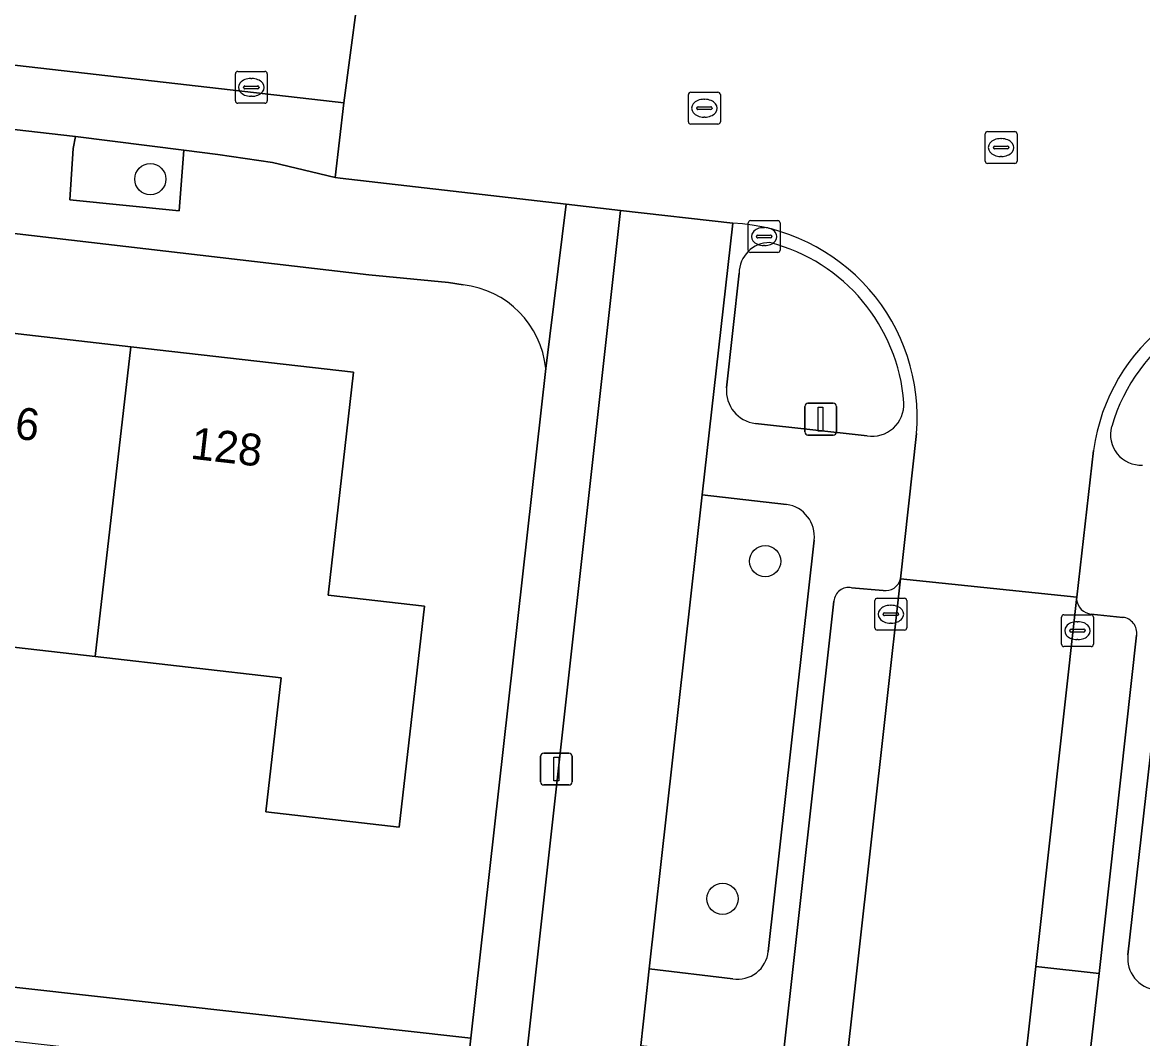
# Model space of a CAD drawing. Extents: x 162026 to 163502, y 387295 to 388169.
# Drawn here: x 162277.28 to 162312.4, y 387953.87 to 387985.75 of the extents above; entities that cross this region are included whole.
import ezdxf

# ---------------------------------------------------------------- set-up
doc = ezdxf.new("R2010")
doc.units = 0
for name, color, linetype in [('IMGEO_Berm_groen', 7, 'Continuous'), ('IMGEO_Boom', 7, 'Continuous'), ('IMGEO_Erf', 7, 'Continuous'), ('IMGEO_Fietspad_gesloten', 7, 'Continuous'), ('IMGEO_Groenvoorziening', 7, 'Continuous'), ('IMGEO_Kolk', 7, 'Continuous'), ('IMGEO_Lichtmast', 7, 'Continuous'), ('IMGEO_Pand', 7, 'Continuous'), ('IMGEO_Pand_nummerreeks', 7, 'Continuous'), ('IMGEO_Parkeervlak_open', 7, 'Continuous'), ('IMGEO_Rijbaan_lokaal_gesloten', 7, 'Continuous'), ('IMGEO_Rijbaan_lokaal_open', 7, 'Continuous'), ('IMGEO_Rioolput', 7, 'Continuous'), ('IMGEO_Voetpad_open', 7, 'Continuous')]:
    doc.layers.add(name, color=color, linetype=linetype)

msp = doc.modelspace()

# ---------------------------------------------------------------- linework, layer by layer
at = {"layer": 'IMGEO_Berm_groen'}
for points in [[(162301.234, 387970.629), (162298.595, 387970.931), (162296.932, 387956.066), (162299.551, 387955.754)], [(162300.663, 387956.611), (162302.1, 387969.506)]]:
    msp.add_lwpolyline(points, dxfattribs=at)
for centre, radius, start, end in [((162301.092, 387969.624), 1.015, 353.3153, 81.9599), ((162299.706, 387956.703), 0.962, 260.7414, 354.5003)]:
    msp.add_arc(centre, radius, start, end, dxfattribs=at)
at = {"layer": 'IMGEO_Boom'}
for centre in [(162281.289, 387980.833), (162300.567, 387968.849), (162299.23, 387958.261)]:
    msp.add_circle(centre, 0.489, dxfattribs=at)
at = {"layer": 'IMGEO_Erf'}
for points in [[(162291.097, 387977.515), (162290.634, 387977.587), (162288.142, 387977.833), (162261.241, 387980.973), (162256.056, 387981.553)], [(162273.693, 387976.378), (162280.678, 387975.578), (162287.661, 387974.779), (162286.86, 387967.781), (162289.888, 387967.434), (162289.095, 387960.507), (162284.908, 387960.986), (162285.39, 387965.195), (162279.564, 387965.862), (162273.794, 387966.523)], [(162239.605, 387969.039), (162246.536, 387968.264), (162245.755, 387961.273), (162248.918, 387960.92), (162252.845, 387960.481), (162252.599, 387958.276), (162260.704, 387957.306), (162291.341, 387953.887), (162293.685, 387974.891)]]:
    msp.add_lwpolyline(points, dxfattribs=at)
msp.add_arc((162290.771, 387974.605), 2.928, 5.6056, 83.6029, dxfattribs=at)
at = {"layer": 'IMGEO_Fietspad_gesloten'}
msp.add_lwpolyline([(162286.582, 387863.057), (162286.832, 387865.282), (162287.035, 387867.097), (162289.894, 387892.691), (162290.021, 387893.825), (162290.158, 387895.051), (162293.257, 387922.839), (162293.487, 387924.906), (162293.703, 387926.861), (162296.667, 387953.66), (162296.814, 387954.996), (162296.932, 387956.066), (162298.595, 387970.931), (162299.549, 387979.456), (162296.034, 387979.848), (162290.464, 387929.711), (162288.097, 387908.488), (162278.956, 387826.545)], dxfattribs=at)
at = {"layer": 'IMGEO_Groenvoorziening'}
msp.add_lwpolyline([(162282.345, 387981.742), (162278.942, 387982.168), (162278.868, 387981.798), (162278.769, 387980.18), (162282.19, 387979.834)], close=True, dxfattribs=at)
for points in [[(162299.746, 387977.882), (162299.356, 387974.287)], [(162300.263, 387973.168), (162303.759, 387972.782)], [(162313.271, 387968.348), (162311.936, 387956.502)]]:
    msp.add_lwpolyline(points, dxfattribs=at)
for centre, radius, start, end in [((162300.712, 387977.877), 0.966, 90.048, 179.714), ((162299.303, 387973.395), 5.628, 4.346, 75.5071), ((162316.871, 387971.493), 5.666, 84.1002, 163.8486), ((162300.383, 387974.192), 1.031, 174.7224, 263.3303), ((162303.915, 387973.77), 1, 261.0367, 2.9103), ((162312.342, 387972.812), 0.95, 164.3094, 273.3573), ((162312.922, 387956.392), 0.992, 173.6196, 263.649)]:
    msp.add_arc(centre, radius, start, end, dxfattribs=at)
at = {"layer": 'IMGEO_Kolk'}
for p, q in [((162283.955, 387983.285), (162283.955, 387984.137)), ((162284.03, 387984.211), (162284.882, 387984.211)), ((162284.443, 387983.991), (162284.468, 387983.991)), ((162284.956, 387984.137), (162284.956, 387983.285)), ((162284.214, 387983.705), (162284.214, 387983.717)), ((162284.652, 387983.668), (162284.254, 387983.668)), ((162284.257, 387983.754), (162284.655, 387983.754)), ((162284.698, 387983.717), (162284.698, 387983.705)), ((162284.466, 387983.431), (162284.441, 387983.431)), ((162284.882, 387983.211), (162284.03, 387983.211)), ((162300.032, 387978.605), (162300.032, 387979.457)), ((162300.107, 387979.531), (162300.959, 387979.531)), ((162301.033, 387979.457), (162301.033, 387978.605)), ((162300.291, 387979.025), (162300.291, 387979.037)), ((162300.334, 387979.074), (162300.732, 387979.074)), ((162300.52, 387979.311), (162300.545, 387979.311)), ((162300.775, 387979.037), (162300.775, 387979.025)), ((162300.729, 387978.988), (162300.331, 387978.988)), ((162300.543, 387978.751), (162300.518, 387978.751)), ((162300.959, 387978.531), (162300.107, 387978.531)), ((162304.006, 387966.76), (162304.006, 387967.612)), ((162304.081, 387967.686), (162304.933, 387967.686)), ((162304.494, 387967.466), (162304.519, 387967.466)), ((162305.007, 387967.612), (162305.007, 387966.76)), ((162304.265, 387967.18), (162304.265, 387967.192)), ((162304.703, 387967.143), (162304.305, 387967.143)), ((162304.308, 387967.229), (162304.706, 387967.229)), ((162304.749, 387967.192), (162304.749, 387967.18)), ((162309.855, 387966.244), (162309.855, 387967.096)), ((162309.93, 387967.17), (162310.782, 387967.17)), ((162310.856, 387967.096), (162310.856, 387966.244)), ((162304.517, 387966.906), (162304.492, 387966.906)), ((162310.343, 387966.95), (162310.368, 387966.95)), ((162304.933, 387966.686), (162304.081, 387966.686)), ((162310.114, 387966.664), (162310.114, 387966.676)), ((162310.552, 387966.627), (162310.154, 387966.627)), ((162310.157, 387966.713), (162310.555, 387966.713)), ((162310.366, 387966.39), (162310.341, 387966.39)), ((162310.598, 387966.676), (162310.598, 387966.664)), ((162310.782, 387966.17), (162309.93, 387966.17))]:
    msp.add_line(p, q, dxfattribs=at)
for points in [[(162283.955, 387983.285), (162283.955, 387984.137)], [(162284.03, 387984.211), (162284.882, 387984.211)], [(162284.956, 387984.137), (162284.956, 387983.285)], [(162284.882, 387983.211), (162284.03, 387983.211)], [(162300.032, 387978.605), (162300.032, 387979.457)], [(162300.107, 387979.531), (162300.959, 387979.531)], [(162301.033, 387979.457), (162301.033, 387978.605)], [(162300.959, 387978.531), (162300.107, 387978.531)], [(162304.006, 387966.76), (162304.006, 387967.612)], [(162304.081, 387967.686), (162304.933, 387967.686)], [(162305.007, 387967.612), (162305.007, 387966.76)], [(162309.855, 387966.244), (162309.855, 387967.096)], [(162309.93, 387967.17), (162310.782, 387967.17)], [(162310.856, 387967.096), (162310.856, 387966.244)], [(162304.933, 387966.686), (162304.081, 387966.686)], [(162310.782, 387966.17), (162309.93, 387966.17)]]:
    msp.add_lwpolyline(points, dxfattribs=at)
for centre, radius, start, end in [((162284.032, 387984.135), 0.0765, 91.552, 178.448), ((162284.032, 387984.135), 0.0765, 91.552, 178.448), ((162284.88, 387984.135), 0.0765, 1.552, 88.448), ((162284.88, 387984.135), 0.0765, 1.552, 88.448), ((162284.254, 387983.714), 0.0403, 85.8775, 175.7526), ((162284.251, 387983.704), 0.0366, 178.938, 274.7102), ((162284.655, 387983.711), 0.043, 264.8664, 352.4533), ((162284.659, 387983.716), 0.0386, 1.7309, 96.639), ((162284.032, 387983.287), 0.0765, 181.552, 268.448), ((162284.032, 387983.287), 0.0765, 181.552, 268.448), ((162284.88, 387983.287), 0.0765, 271.552, 358.448), ((162284.88, 387983.287), 0.0765, 271.552, 358.448), ((162300.109, 387979.455), 0.0765, 91.552, 178.448), ((162300.109, 387979.455), 0.0765, 91.552, 178.448), ((162300.957, 387979.455), 0.0765, 1.552, 88.448), ((162300.957, 387979.455), 0.0765, 1.552, 88.448), ((162300.331, 387979.034), 0.0403, 85.8775, 175.7526), ((162300.736, 387979.036), 0.0386, 1.7309, 96.639), ((162300.328, 387979.024), 0.0366, 178.938, 274.7102), ((162300.732, 387979.031), 0.043, 264.8664, 352.4533), ((162300.109, 387978.607), 0.0765, 181.552, 268.448), ((162300.109, 387978.607), 0.0765, 181.552, 268.448), ((162300.957, 387978.607), 0.0765, 271.552, 358.448), ((162300.957, 387978.607), 0.0765, 271.552, 358.448), ((162304.083, 387967.61), 0.0765, 91.552, 178.448), ((162304.083, 387967.61), 0.0765, 91.552, 178.448), ((162304.931, 387967.61), 0.0765, 1.552, 88.448), ((162304.931, 387967.61), 0.0765, 1.552, 88.448), ((162304.305, 387967.189), 0.0403, 85.8775, 175.7526), ((162304.302, 387967.179), 0.0366, 178.938, 274.7102), ((162304.706, 387967.186), 0.043, 264.8664, 352.4533), ((162304.71, 387967.191), 0.0386, 1.7309, 96.639), ((162309.932, 387967.094), 0.0765, 91.552, 178.448), ((162309.932, 387967.094), 0.0765, 91.552, 178.448), ((162310.78, 387967.094), 0.0765, 1.552, 88.448), ((162310.78, 387967.094), 0.0765, 1.552, 88.448), ((162304.083, 387966.762), 0.0765, 181.552, 268.448), ((162304.083, 387966.762), 0.0765, 181.552, 268.448), ((162304.931, 387966.762), 0.0765, 271.552, 358.448), ((162304.931, 387966.762), 0.0765, 271.552, 358.448), ((162310.154, 387966.673), 0.0403, 85.8775, 175.7526), ((162310.151, 387966.663), 0.0366, 178.938, 274.7102), ((162310.555, 387966.67), 0.043, 264.8664, 352.4533), ((162310.559, 387966.675), 0.0386, 1.7309, 96.639), ((162309.932, 387966.246), 0.0765, 181.552, 268.448), ((162309.932, 387966.246), 0.0765, 181.552, 268.448), ((162310.78, 387966.246), 0.0765, 271.552, 358.448), ((162310.78, 387966.246), 0.0765, 271.552, 358.448)]:
    msp.add_arc(centre, radius, start, end, dxfattribs=at)
for centre, major_axis, ratio, start_param, end_param in [((162284.442, 387983.711), (-0.387, 0.002), 0.722429, 4.712389, 7.853982), ((162284.467, 387983.711), (-0.39, 0.002), 0.717154, 1.570796, 4.712389), ((162300.519, 387979.031), (-0.387, 0.002), 0.722429, 4.712389, 7.853982), ((162300.544, 387979.031), (-0.39, 0.002), 0.717154, 1.570796, 4.712389), ((162304.493, 387967.186), (-0.387, 0.002), 0.722429, 4.712389, 7.853982), ((162304.518, 387967.186), (-0.39, 0.002), 0.717154, 1.570796, 4.712389), ((162310.342, 387966.67), (-0.387, 0.002), 0.722429, 4.712389, 7.853982), ((162310.367, 387966.67), (-0.39, 0.002), 0.717154, 1.570796, 4.712389)]:
    msp.add_ellipse(centre, major_axis=major_axis, ratio=ratio, start_param=start_param, end_param=end_param, dxfattribs=at)
at = {"layer": 'IMGEO_Lichtmast'}
for p, q in [((162301.907, 387973.802), (162302.697, 387973.802)), ((162302.697, 387973.802), (162301.907, 387973.802)), ((162301.807, 387972.902), (162301.807, 387973.702)), ((162301.807, 387973.702), (162301.807, 387972.902)), ((162302.797, 387973.702), (162302.797, 387972.902)), ((162302.797, 387972.902), (162302.797, 387973.702)), ((162302.697, 387972.802), (162301.907, 387972.802)), ((162301.907, 387972.802), (162302.697, 387972.802)), ((162293.522, 387961.93), (162293.522, 387962.73)), ((162293.522, 387962.73), (162293.522, 387961.93)), ((162293.622, 387962.83), (162294.412, 387962.83)), ((162294.412, 387962.83), (162293.622, 387962.83)), ((162294.512, 387962.73), (162294.512, 387961.93)), ((162294.512, 387961.93), (162294.512, 387962.73)), ((162294.412, 387961.83), (162293.622, 387961.83)), ((162293.622, 387961.83), (162294.412, 387961.83))]:
    msp.add_line(p, q, dxfattribs=at)
for points in [[(162302.227, 387973.677), (162302.377, 387973.677), (162302.377, 387972.927), (162302.227, 387972.927), (162302.227, 387973.677)], [(162293.942, 387962.705), (162294.092, 387962.705), (162294.092, 387961.955), (162293.942, 387961.955), (162293.942, 387962.705)]]:
    msp.add_lwpolyline(points, dxfattribs=at)
for centre, start, end in [((162301.907, 387973.702), 90, 180), ((162301.907, 387973.702), 90, 180), ((162302.697, 387973.702), 0, 90), ((162302.697, 387973.702), 360, 90), ((162301.907, 387972.902), 180, 270), ((162301.907, 387972.902), 180, 270), ((162302.697, 387972.902), 270, 0), ((162302.697, 387972.902), 270, 0), ((162293.622, 387962.73), 90, 180), ((162293.622, 387962.73), 90, 180), ((162294.412, 387962.73), 0, 90), ((162294.412, 387962.73), 360, 90), ((162293.622, 387961.93), 180, 270), ((162293.622, 387961.93), 180, 270), ((162294.412, 387961.93), 270, 0), ((162294.412, 387961.93), 270, 0)]:
    msp.add_arc(centre, 0.1, start, end, dxfattribs=at)
at = {"layer": 'IMGEO_Pand'}
for points in [[(162280.678, 387975.578), (162273.693, 387976.378), (162272.883, 387969.3), (162269.935, 387969.637), (162269.152, 387962.798), (162273.313, 387962.322), (162273.794, 387966.523), (162279.564, 387965.862)], [(162279.564, 387965.862), (162285.39, 387965.195), (162284.908, 387960.986), (162289.095, 387960.507), (162289.888, 387967.434), (162286.86, 387967.781), (162287.661, 387974.779), (162280.678, 387975.578)]]:
    msp.add_lwpolyline(points, close=True, dxfattribs=at)
at = {"layer": 'IMGEO_Parkeervlak_open'}
msp.add_lwpolyline([(162287.36, 387983.225), (162274.652, 387984.68), (162274.447, 387982.68), (162278.942, 387982.168), (162282.345, 387981.742), (162283.404, 387981.609), (162285.117, 387981.352), (162287.087, 387980.885)], close=True, dxfattribs=at)
for points in [[(162302.723, 387967.594), (162294.303, 387892.007), (162291.572, 387867.15), (162293.541, 387866.933), (162296.246, 387891.427), (162304.811, 387968.292)], [(162304.263, 387967.93), (162303.277, 387968.016)], [(162310.325, 387967.647), (162309.047, 387956.134), (162311.038, 387955.913), (162312.212, 387966.528)], [(162311.777, 387967.088), (162310.787, 387967.188)]]:
    msp.add_lwpolyline(points, dxfattribs=at)
for centre, radius, start, end in [((162304.333, 387968.419), 0.494, 261.8083, 345.0879), ((162303.186, 387967.561), 0.464, 78.7022, 175.8932), ((162310.852, 387967.716), 0.532, 187.4211, 262.9522), ((162311.723, 387966.597), 0.494, 351.9363, 83.7428)]:
    msp.add_arc(centre, radius, start, end, dxfattribs=at)
at = {"layer": 'IMGEO_Rijbaan_lokaal_gesloten'}
for points in [[(162300.788, 387986.479), (162300.294, 387986.533), (162296.82, 387986.925), (162294.103, 387987.216), (162288.149, 387987.855), (162287.971, 387987.874), (162287.36, 387983.225), (162287.087, 387980.885), (162287.244, 387980.867), (162294.331, 387980.045), (162296.034, 387979.848), (162299.549, 387979.456)], [(162305.312, 387972.855), (162304.811, 387968.292), (162310.334, 387967.724), (162310.861, 387972.324)], [(162298.53, 387861.44), (162299.054, 387866.158), (162302.841, 387900.241), (162308.539, 387951.558), (162309.047, 387956.134), (162310.325, 387967.647), (162310.334, 387967.724), (162304.811, 387968.292), (162296.246, 387891.427), (162293.541, 387866.933), (162293.019, 387862.21)]]:
    msp.add_lwpolyline(points, dxfattribs=at)
for centre, radius, start, end in [((162299.225, 387973.357), 6.108, 355.289, 86.9561), ((162316.878, 387971.502), 6.073, 82.8268, 172.2196)]:
    msp.add_arc(centre, radius, start, end, dxfattribs=at)
at = {"layer": 'IMGEO_Rijbaan_lokaal_open'}
msp.add_lwpolyline([(162256.533, 387986.755), (162268.637, 387985.369), (162274.652, 387984.68), (162287.36, 387983.225), (162287.971, 387987.874), (162285.183, 387988.176), (162261.021, 387990.93)], dxfattribs=at)
at = {"layer": 'IMGEO_Rioolput'}
for p, q in [((162298.159, 387982.631), (162298.159, 387983.483)), ((162298.234, 387983.557), (162299.086, 387983.557)), ((162298.647, 387983.337), (162298.672, 387983.337)), ((162299.16, 387983.483), (162299.16, 387982.631)), ((162298.418, 387983.051), (162298.418, 387983.063)), ((162298.856, 387983.014), (162298.458, 387983.014)), ((162298.461, 387983.1), (162298.859, 387983.1)), ((162298.902, 387983.063), (162298.902, 387983.051)), ((162299.086, 387982.557), (162298.234, 387982.557)), ((162298.67, 387982.777), (162298.645, 387982.777)), ((162307.461, 387981.397), (162307.461, 387982.249)), ((162307.536, 387982.323), (162308.388, 387982.323)), ((162308.462, 387982.249), (162308.462, 387981.397)), ((162307.763, 387981.866), (162308.161, 387981.866)), ((162307.949, 387982.103), (162307.974, 387982.103)), ((162307.72, 387981.817), (162307.72, 387981.829)), ((162308.158, 387981.78), (162307.76, 387981.78)), ((162307.972, 387981.543), (162307.947, 387981.543)), ((162308.204, 387981.829), (162308.204, 387981.817)), ((162308.388, 387981.323), (162307.536, 387981.323))]:
    msp.add_line(p, q, dxfattribs=at)
for points in [[(162298.159, 387982.631), (162298.159, 387983.483)], [(162298.234, 387983.557), (162299.086, 387983.557)], [(162299.16, 387983.483), (162299.16, 387982.631)], [(162299.086, 387982.557), (162298.234, 387982.557)], [(162307.461, 387981.397), (162307.461, 387982.249)], [(162307.536, 387982.323), (162308.388, 387982.323)], [(162308.462, 387982.249), (162308.462, 387981.397)], [(162308.388, 387981.323), (162307.536, 387981.323)]]:
    msp.add_lwpolyline(points, dxfattribs=at)
for centre, radius, start, end in [((162298.236, 387983.481), 0.0765, 91.552, 178.448), ((162298.236, 387983.481), 0.0765, 91.552, 178.448), ((162299.084, 387983.481), 0.0765, 1.552, 88.448), ((162299.084, 387983.481), 0.0765, 1.552, 88.448), ((162298.458, 387983.06), 0.0403, 85.8775, 175.7526), ((162298.455, 387983.05), 0.0366, 178.938, 274.7102), ((162298.859, 387983.057), 0.043, 264.8664, 352.4533), ((162298.863, 387983.062), 0.0386, 1.7309, 96.639), ((162298.236, 387982.633), 0.0765, 181.552, 268.448), ((162298.236, 387982.633), 0.0765, 181.552, 268.448), ((162299.084, 387982.633), 0.0765, 271.552, 358.448), ((162299.084, 387982.633), 0.0765, 271.552, 358.448), ((162307.538, 387982.247), 0.0765, 91.552, 178.448), ((162307.538, 387982.247), 0.0765, 91.552, 178.448), ((162308.386, 387982.247), 0.0765, 1.552, 88.448), ((162308.386, 387982.247), 0.0765, 1.552, 88.448), ((162307.76, 387981.826), 0.0403, 85.8775, 175.7526), ((162308.165, 387981.828), 0.0386, 1.7309, 96.639), ((162307.757, 387981.816), 0.0366, 178.938, 274.7102), ((162308.161, 387981.823), 0.043, 264.8664, 352.4533), ((162307.538, 387981.399), 0.0765, 181.552, 268.448), ((162307.538, 387981.399), 0.0765, 181.552, 268.448), ((162308.386, 387981.399), 0.0765, 271.552, 358.448), ((162308.386, 387981.399), 0.0765, 271.552, 358.448)]:
    msp.add_arc(centre, radius, start, end, dxfattribs=at)
for centre, major_axis, ratio, start_param, end_param in [((162298.646, 387983.057), (-0.387, 0.002), 0.722429, 4.712389, 7.853982), ((162298.671, 387983.057), (-0.39, 0.002), 0.717154, 1.570796, 4.712389), ((162307.948, 387981.823), (-0.387, 0.002), 0.722429, 4.712389, 7.853982), ((162307.973, 387981.823), (-0.39, 0.002), 0.717154, 1.570796, 4.712389)]:
    msp.add_ellipse(centre, major_axis=major_axis, ratio=ratio, start_param=start_param, end_param=end_param, dxfattribs=at)
at = {"layer": 'IMGEO_Voetpad_open'}
for points in [[(162293.685, 387974.891), (162294.331, 387980.045), (162287.244, 387980.867), (162287.087, 387980.885), (162285.117, 387981.352), (162283.404, 387981.609), (162282.345, 387981.742), (162282.19, 387979.834), (162278.769, 387980.18), (162278.868, 387981.798), (162278.942, 387982.168), (162274.447, 387982.68), (162268.419, 387983.366), (162263.824, 387983.889), (162263.585, 387981.924), (162258.806, 387982.466), (162259.028, 387984.445), (162256.295, 387984.784)], [(162256.056, 387981.553), (162261.241, 387980.973), (162288.142, 387977.833), (162290.634, 387977.587), (162291.097, 387977.515)], [(162278.372, 387825.72), (162278.87, 387825.665), (162278.956, 387826.545), (162288.097, 387908.488), (162290.464, 387929.711), (162296.034, 387979.848), (162294.331, 387980.045), (162293.685, 387974.891), (162291.341, 387953.887), (162291.153, 387952.205), (162285.089, 387897.861), (162281.859, 387868.778), (162281.738, 387867.693), (162278.721, 387840.526)], [(162299.549, 387979.456), (162298.595, 387970.931), (162301.234, 387970.629)], [(162299.356, 387974.287), (162299.746, 387977.882)], [(162303.759, 387972.782), (162300.263, 387973.168)], [(162304.811, 387968.292), (162305.312, 387972.855)], [(162310.861, 387972.324), (162310.334, 387967.724), (162310.325, 387967.647)], [(162302.1, 387969.506), (162300.663, 387956.611)], [(162311.936, 387956.502), (162313.271, 387968.348)], [(162303.277, 387968.016), (162304.263, 387967.93)], [(162288.265, 387837.556), (162291.036, 387862.429), (162291.572, 387867.15), (162294.303, 387892.007), (162302.723, 387967.594)], [(162310.787, 387967.188), (162311.777, 387967.088)], [(162312.212, 387966.528), (162311.038, 387955.913), (162310.512, 387951.338), (162304.798, 387900.046), (162301.044, 387865.937), (162300.507, 387861.221), (162297.786, 387836.544)], [(162299.551, 387955.754), (162296.932, 387956.066), (162296.814, 387954.996), (162296.667, 387953.66), (162299.304, 387953.372)]]:
    msp.add_lwpolyline(points, dxfattribs=at)
for points in [[(162260.704, 387957.306), (162260.527, 387955.775), (162266.39, 387955.112), (162276.462, 387953.862), (162285.289, 387952.859), (162291.153, 387952.205), (162291.341, 387953.887)], [(162311.038, 387955.913), (162309.047, 387956.134), (162308.539, 387951.558), (162310.512, 387951.338)]]:
    msp.add_lwpolyline(points, close=True, dxfattribs=at)
for centre, radius, start, end in [((162299.225, 387973.357), 6.108, 355.289, 86.9561), ((162300.712, 387977.877), 0.966, 90.048, 179.714), ((162299.303, 387973.395), 5.628, 4.346, 75.5071), ((162290.771, 387974.605), 2.928, 5.6056, 83.6029), ((162316.878, 387971.502), 6.073, 82.8268, 172.2196), ((162316.871, 387971.493), 5.666, 84.1002, 163.8486), ((162300.383, 387974.192), 1.031, 174.7224, 263.3303), ((162303.915, 387973.77), 1, 261.0367, 2.9103), ((162312.342, 387972.812), 0.95, 164.3094, 273.3573), ((162301.092, 387969.624), 1.015, 353.3153, 81.9599), ((162304.333, 387968.419), 0.494, 261.8083, 345.0879), ((162303.186, 387967.561), 0.464, 78.7022, 175.8932), ((162310.852, 387967.716), 0.532, 187.4211, 262.9522), ((162311.723, 387966.597), 0.494, 351.9363, 83.7428), ((162299.706, 387956.703), 0.962, 260.7414, 354.5003), ((162312.922, 387956.392), 0.992, 173.6196, 263.649)]:
    msp.add_arc(centre, radius, start, end, dxfattribs=at)

# ---------------------------------------------------------------- texts
at = {"layer": 'IMGEO_Pand_nummerreeks'}
for s, p in [('126', (162275.533, 387972.866)), ('128', (162282.521, 387972.067))]:
    msp.add_text(s, height=1, rotation=353.4694, dxfattribs=at).set_placement(p)

doc.saveas('drawing.dxf')
